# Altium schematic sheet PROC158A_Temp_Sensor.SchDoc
size 431 x 279 mm; Date: Not shown in title block; ApprovedBy: Not shown in title block; CheckedBy: Not shown in title block; Author: Not shown in title block; CompanyName: Not shown in title block; Engineer: Not shown in title block; Organization: Not shown in title block; Address1: Not shown in title block; Address2: Not shown in title block; Address3: Not shown in title block; Address4: Not shown in title block; DocumentNumber: 24; Revision: Use project parameter SCH_Rev; SheetNumber: 23; SheetTotal: 24; PageSetup: Record=PageOptions¦CenterHorizontal=True¦CenterVertical=True¦PrintScale=1.00¦XCorrection=1.00¦YCorrection=1.00¦PrintKind=0¦BorderSize=5000000¦LeftOffset=0¦BottomOffset=0¦Orientation=2¦PaperLength=1000¦PaperWidth=1000¦Scale=100¦PaperSource=15¦PrintQuality=600¦MediaType=1¦DitherType=10¦PaperKind=Letter¦PrintScaleMode=1
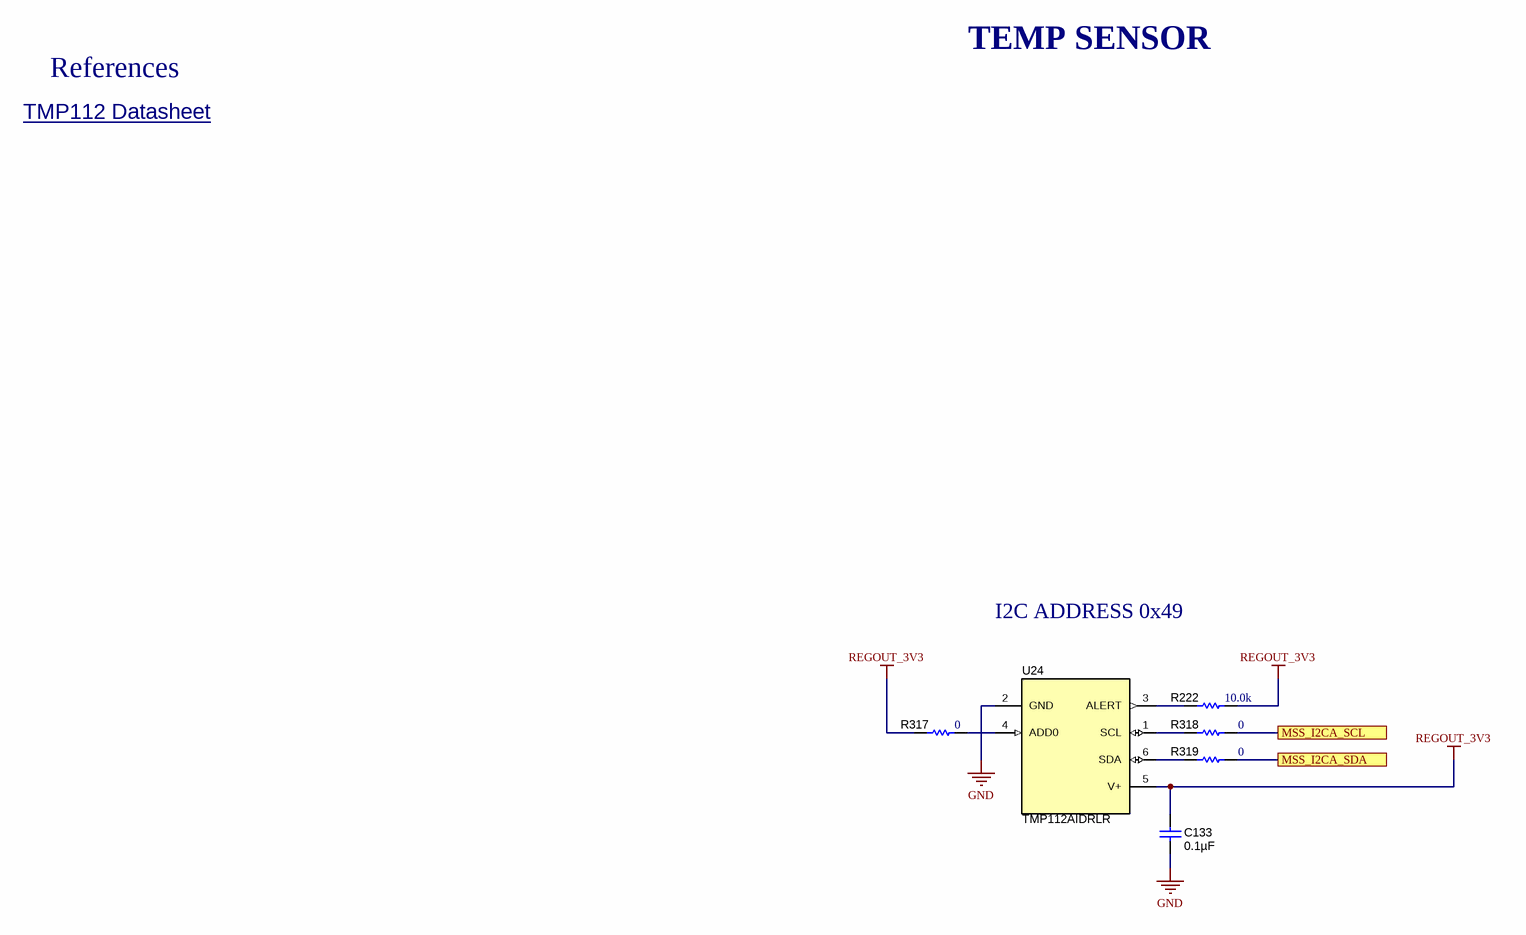
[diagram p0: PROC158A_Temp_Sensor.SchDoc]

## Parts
C133  ValueDisplayed: 0.1µF  [0402L]  (hidden comment: C0402C104K8RACTU)
R222  ValueDisplayed: 10.0k  [0402L]  (hidden comment: CRCW040210K0FKED)
R317  ValueDisplayed: 0  [0201L]  (hidden comment: CRCW02010000Z0ED)
R318  ValueDisplayed: 0  [0201L]  (hidden comment: CRCW02010000Z0ED)
R319  ValueDisplayed: 0  [0201L]  (hidden comment: CRCW02010000Z0ED)
U24  TMP112AIDRLR  [DRL0006A]

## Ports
MSS_I2CA_SCL, MSS_I2CA_SDA

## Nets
GND: C133.2 U24.2(GND)
REGOUT_3V3: C133.1 R222.2 R317.1 U24.5(V+)
MSS_I2CA_SCL: R318.1 ; port MSS_I2CA_SCL
MSS_I2CA_SDA: R319.2 ; port MSS_I2CA_SDA
NetR222_1: R222.1 U24.3(ALERT)
NetR317_2: R317.2 U24.4(ADD0)
NetR318_2: R318.2 U24.1(SCL)
NetR319_1: R319.1 U24.6(SDA)

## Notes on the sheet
- TEMP SENSOR
- References
- TMP112 Datasheet <http://www.ti.com/lit/ds/symlink/tmp112.pdf>
- I2C ADDRESS 0x49

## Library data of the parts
C133 = CMP-0078241-1: CAP, CERM, 0.1 µF, 10 V,+/- 10%, X7R, 0402; Manufacturer: Kemet; TaMin_C: -55°C; Polarized: N; SizeAreaWB_mm2: 3; U/M: EA; Value: 0.1uF; TaMax_C: 125°C; SizeZ_mm: 0.6; SizeX_mm: 1; SizeY_mm: 0.5; Cap_Case: 0402; Value2: 10V; Cap_F: 100nF; AEC Category: Q200
R222 = CMP-0025958-3: RES, 10.0 k, 1%, 0.063 W, AEC-Q200 Grade 0, 0402; Manufacturer: Vishay-Dale; Power_W: 63mW; TempCo: 100 ppm/C; Value_Code: 10k0; Value: 10.0k; EIA_Code: E96; Res_ohm: 10k; SizeX_mm: 1; SizeY_mm: 0.5; SizeZ_mm: 0.6; Value2: 0.063W; AEC Qualified: Y; VDC_V: 50V; AEC Category: Q200; AEC Grade: 0
R317-R319 = CMP-0027008-4: RES, 0, 5%, 0.05 W, 0201; Manufacturer: Vishay-Dale; Power_W: 50mW; TempCo: ppm/C; Value_Code: 0000; Value: 0; EIA_Code: E24; SizeX_mm: 0.6; SizeY_mm: 0.3; SizeZ_mm: 0.26; Value2: 0.05W; SizeArea_mm2: 0.18; AEC Qualified: N; AEC Category: Q200
U24 = CMP-0067397-2: 1.4V-Capable +/-0.5degC Temperature Sensor with Alert Function and I2C/SMBus interface in SOT-563, DRL0006A (SOT-OTHER-6); Alternate PartNumber: TMP112AIDRLT; Alternate Manufacturer: Texas Instruments; Green_Lifecycle: Active; SizeAreaWB_mm2: 6.76; Green_REACh: Passed; U/M: EA; SizeZ_mm: 0.6; SizeX_mm: 1.6; SizeArea_mm2: 2.56; CompType: IC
